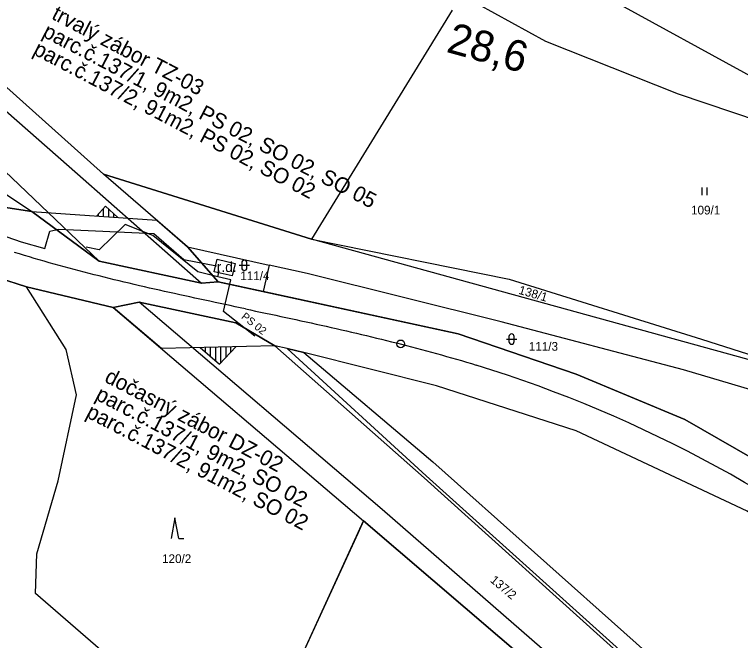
# Model space of a CAD drawing. Extents: x -794765 to -785424, y -1118958 to -1108731.
# Drawn here: x -789643.6 to -789502.2, y -1114356.2 to -1114234.4 of the extents above; entities that cross this region are included whole.
import ezdxf

# ---------------------------------------------------------------- set-up
doc = ezdxf.new("R2010")
doc.units = 0
for name, color, linetype in [('Level 66', 7, 'Continuous'), ('Level 73', 7, 'Continuous'), ('Level 75', 7, 'Continuous'), ('Level 76', 7, 'Continuous'), ('Level 77', 7, 'Continuous'), ('Level 81', 7, 'Continuous'), ('Vrstva 1', 7, 'Continuous'), ('Vrstva 53', 7, 'Continuous')]:
    doc.layers.add(name, color=color, linetype=linetype)

msp = doc.modelspace()

# ---------------------------------------------------------------- linework, layer by layer
at = {"layer": 'Level 66'}
for p, q in [((-789509.7, -1114269.49), (-789509.7, -1114267.99)), ((-789508.7, -1114269.49), (-789508.7, -1114267.99)), ((-789599.82, -1114283.16), (-789597.81, -1114283.16)), ((-789599.32, -1114282.66), (-789599.32, -1114283.66)), ((-789598.31, -1114283.66), (-789598.31, -1114282.66)), ((-789547.79, -1114297.52), (-789545.79, -1114297.52)), ((-789547.29, -1114297.02), (-789547.29, -1114298.02)), ((-789546.29, -1114298.02), (-789546.29, -1114297.02)), ((-789612.34, -1114332.34), (-789613.09, -1114336.34)), ((-789611.59, -1114336.34), (-789612.34, -1114332.34)), ((-789611.59, -1114336.34), (-789610.59, -1114336.34))]:
    msp.add_line(p, q, dxfattribs=at)
for centre, start, end in [((-789598.82, -1114282.66), 0, 180), ((-789598.82, -1114283.66), 180, 359.9879), ((-789546.79, -1114297.02), 0, 180), ((-789546.79, -1114298.02), 180, 359.9879)]:
    msp.add_arc(centre, 0.5, start, end, dxfattribs=at)
at = {"layer": 'Level 75'}
for p, q in [((-789495.83, -1114248.83), (-789550.41, -1114218.8)), ((-789558.36, -1114233.53), (-789585.72, -1114278.05)), ((-789652.15, -1114264.75), (-789640.19, -1114272.7)), ((-789609.87, -1114279.55), (-789626.24, -1114265.44)), ((-789585.72, -1114278.05), (-789626.24, -1114265.44)), ((-789672.68, -1114277.31), (-789641.23, -1114287.32)), ((-789475.21, -1114308.57), (-789585.72, -1114278.05)), ((-789603.91, -1114286.39), (-789609.87, -1114279.55)), ((-789609.87, -1114279.55), (-789594.01, -1114283.11)), ((-789594.01, -1114283.11), (-789595.15, -1114288.29)), ((-789595.15, -1114288.29), (-789603.91, -1114286.39)), ((-789641.23, -1114287.32), (-789624.34, -1114291.37)), ((-789624.34, -1114291.37), (-789575.6, -1114332.86)), ((-789590.47, -1114299.37), (-789587.26, -1114300.1)), ((-789599.87, -1114385.78), (-789575.6, -1114332.86))]:
    msp.add_line(p, q, dxfattribs=at)
for points in [[(-789626.24, -1114265.44), (-789653.29, -1114241.26), (-789699.87, -1114199.39)], [(-789640.19, -1114272.7), (-789665.23, -1114268.84), (-789691.28, -1114256.01), (-789717.72, -1114240.35)], [(-789640.19, -1114272.7), (-789627.07, -1114282.33), (-789607.19, -1114286.63), (-789603.91, -1114286.39)], [(-789585.72, -1114278.05), (-789547.28, -1114285.86), (-789509.8, -1114297.51), (-789475.21, -1114308.57)], [(-789483.32, -1114312.4), (-789513.31, -1114303.51), (-789548.79, -1114294.18), (-789586.59, -1114284.77), (-789594.01, -1114283.11)], [(-789599.87, -1114385.78), (-789620.14, -1114369.54), (-789622.91, -1114361.34), (-789639.49, -1114347.05), (-789639.25, -1114339.29), (-789635.04, -1114325.1), (-789631.47, -1114308.38), (-789633.53, -1114299.52), (-789641.23, -1114287.32)], [(-789496.46, -1114322.71), (-789513.07, -1114313.2), (-789534.19, -1114304.37), (-789557.19, -1114296.51), (-789595.15, -1114288.29)], [(-789590.47, -1114299.37), (-789592.9, -1114298.82), (-789600.46, -1114294.39), (-789619.3, -1114290.36), (-789624.34, -1114291.37)], [(-789411.55, -1114487.64), (-789444.12, -1114440.1), (-789460.39, -1114416.23), (-789471.74, -1114406.17), (-789505.63, -1114376.09), (-789563.4, -1114324.15), (-789590.47, -1114299.37)], [(-789587.26, -1114300.1), (-789562.09, -1114321.4), (-789502.74, -1114374.33), (-789470.17, -1114403.72), (-789452.65, -1114419.15), (-789441.48, -1114438.37), (-789411.55, -1114487.64)], [(-789387.36, -1114439.86), (-789400.13, -1114420.69), (-789449.47, -1114371.56), (-789470.68, -1114352.09), (-789500.91, -1114330.99), (-789534.18, -1114315.38), (-789561.38, -1114306.6), (-789587.26, -1114300.1)], [(-789575.6, -1114332.86), (-789515.81, -1114384.07), (-789480.88, -1114415.35), (-789466.19, -1114428.84), (-789454.55, -1114445.52), (-789423.09, -1114499.54)]]:
    msp.add_lwpolyline(points, dxfattribs=at)
at = {"layer": 'Level 77'}
for p, q in [((-789656.61, -1114243.22), (-789631.32, -1114265.33)), ((-789627.07, -1114282.33), (-789662.93, -1114248.27)), ((-789631.32, -1114265.33), (-789607.19, -1114286.63)), ((-789572, -1114330.7), (-789619.3, -1114290.36)), ((-789592.9, -1114298.82), (-789563.81, -1114324.53)), ((-789563.81, -1114324.53), (-789505.98, -1114376.61)), ((-789512.77, -1114382.14), (-789572, -1114330.7))]:
    msp.add_line(p, q, dxfattribs=at)
at = {"layer": 'Level 81'}
for points in [[(-789863.72, -1114054.97), (-789859.91, -1114056.9), (-789828.1, -1114085.48), (-789766.83, -1114142.08), (-789706.12, -1114193.77), (-789699.87, -1114199.39), (-789653.29, -1114241.26), (-789626.24, -1114265.44), (-789585.72, -1114278.05), (-789547.28, -1114285.86), (-789509.8, -1114297.51), (-789475.21, -1114308.57), (-789456.17, -1114314.65), (-789451.67, -1114316.09), (-789445.82, -1114299.21), (-789436.06, -1114282.16), (-789435.21, -1114282.44), (-789432.19, -1114273.58), (-789444.18, -1114268.92), (-789455.16, -1114266.24)], [(-789455.16, -1114266.24), (-789471.09, -1114264.39), (-789472.14, -1114264.04), (-789514.28, -1114249.87), (-789540.11, -1114239.63), (-789556.69, -1114230.44)], [(-789400.13, -1114420.69), (-789449.47, -1114371.56), (-789470.68, -1114352.09), (-789500.91, -1114330.99), (-789534.18, -1114315.38), (-789561.38, -1114306.6), (-789587.26, -1114300.1), (-789562.09, -1114321.4), (-789502.74, -1114374.33), (-789470.17, -1114403.72), (-789452.65, -1114419.15), (-789441.48, -1114438.37), (-789411.55, -1114487.64), (-789407.91, -1114493.28)], [(-789417.6, -1114507.26), (-789420.43, -1114503.28), (-789423.09, -1114499.54), (-789454.55, -1114445.52), (-789466.19, -1114428.84), (-789480.88, -1114415.35), (-789515.81, -1114384.07), (-789575.6, -1114332.86), (-789576.73, -1114335.33), (-789599.87, -1114385.78), (-789603.26, -1114393.19), (-789604.86, -1114396.67)]]:
    msp.add_lwpolyline(points, dxfattribs=at)
at = {"layer": 'Vrstva 1'}
for p, q in [((-789627.58, -1114273.58), (-789625.82, -1114271.66)), ((-789626.21, -1114273.68), (-789626.21, -1114272.09)), ((-789625.82, -1114271.66), (-789623.43, -1114273.87)), ((-789625.21, -1114273.75), (-789625.21, -1114272.22)), ((-789640.19, -1114272.7), (-789627.07, -1114282.33)), ((-789640.19, -1114272.7), (-789615.84, -1114274.4)), ((-789627.21, -1114273.61), (-789627.21, -1114273.18)), ((-789624.21, -1114273.82), (-789624.21, -1114273.15)), ((-789637.05, -1114275), (-789637.05, -1114275)), ((-789622.02, -1114275.21), (-789627.1, -1114280.14)), ((-789622.02, -1114275.21), (-789627.1, -1114280.14)), ((-789616.62, -1114277.34), (-789622.02, -1114275.21)), ((-789607.89, -1114284.46), (-789616.62, -1114277.34)), ((-789627.1, -1114280.14), (-789629.63, -1114279.65)), ((-789627.1, -1114280.14), (-789629.63, -1114279.65)), ((-789609.87, -1114279.55), (-789609.87, -1114279.55)), ((-789609.87, -1114279.55), (-789603.91, -1114286.39)), ((-789627.07, -1114282.33), (-789607.19, -1114286.63)), ((-789604.67, -1114284.43), (-789604.11, -1114282)), ((-789604.67, -1114284.43), (-789604.11, -1114282)), ((-789604.11, -1114282), (-789600.6, -1114282.8)), ((-789604.11, -1114282), (-789600.6, -1114282.8)), ((-789600.6, -1114282.8), (-789601.16, -1114285.24)), ((-789600.6, -1114282.8), (-789601.16, -1114285.24)), ((-789604, -1114285.39), (-789607.89, -1114284.46)), ((-789604, -1114285.39), (-789607.89, -1114284.46)), ((-789604, -1114285.39), (-789607.89, -1114284.46)), ((-789601.16, -1114285.24), (-789604.67, -1114284.43)), ((-789601.16, -1114285.24), (-789604.67, -1114284.43)), ((-789607.19, -1114286.63), (-789603.91, -1114286.39)), ((-789624.34, -1114291.37), (-789619.3, -1114290.36)), ((-789619.3, -1114290.36), (-789600.46, -1114294.39)), ((-789602.15, -1114294.03), (-789602.15, -1114294.03)), ((-789600.46, -1114294.39), (-789592.9, -1114298.82)), ((-789592.9, -1114298.82), (-789614.97, -1114299.35)), ((-789607.41, -1114299.17), (-789603.64, -1114302.43)), ((-789606.38, -1114300.06), (-789606.38, -1114299.14)), ((-789605.38, -1114300.92), (-789605.38, -1114299.12)), ((-789604.38, -1114301.79), (-789604.38, -1114299.09)), ((-789603.64, -1114302.43), (-789600.5, -1114299)), ((-789603.38, -1114302.15), (-789603.38, -1114299.07)), ((-789602.38, -1114301.05), (-789602.38, -1114299.05)), ((-789601.42, -1114300.01), (-789601.42, -1114299.02))]:
    msp.add_line(p, q, dxfattribs=at)
for points in [[(-789729.37, -1114235.18), (-789723.86, -1114238), (-789721.43, -1114240.25), (-789715.58, -1114243.5), (-789712.53, -1114244.57), (-789693.8, -1114256.22), (-789674.69, -1114266.08), (-789667.23, -1114269.28), (-789659.83, -1114272.47), (-789642.29, -1114278.58), (-789637.66, -1114279.92), (-789636.67, -1114276.5), (-789634.93, -1114276.11), (-789616.44, -1114277), (-789610.6, -1114282.06), (-789604.23, -1114283.25)], [(-789729.37, -1114235.18), (-789723.86, -1114238), (-789721.43, -1114240.25), (-789715.58, -1114243.5), (-789712.53, -1114244.57), (-789693.8, -1114256.22), (-789674.69, -1114266.08), (-789667.23, -1114269.28), (-789659.83, -1114272.47), (-789642.29, -1114278.58), (-789637.66, -1114279.92), (-789636.67, -1114276.5), (-789634.93, -1114276.11), (-789616.44, -1114277), (-789610.6, -1114282.06), (-789604.23, -1114283.25)], [(-789667.23, -1114269.28), (-789659.83, -1114272.47), (-789642.29, -1114278.58), (-789637.66, -1114279.92), (-789636.67, -1114276.5), (-789634.93, -1114276.11), (-789616.44, -1114277), (-789610.6, -1114282.06), (-789604.23, -1114283.25)], [(-789667.23, -1114269.28), (-789659.83, -1114272.47), (-789642.29, -1114278.58), (-789637.66, -1114279.92), (-789636.67, -1114276.5), (-789634.93, -1114276.11), (-789616.44, -1114277), (-789610.6, -1114282.06), (-789604.23, -1114283.25)], [(-789667.23, -1114269.28), (-789659.83, -1114272.47), (-789642.29, -1114278.58), (-789637.66, -1114279.92), (-789636.67, -1114276.5), (-789634.93, -1114276.11), (-789616.44, -1114277), (-789610.6, -1114282.06), (-789604.23, -1114283.25)], [(-789598.62, -1114291.64), (-789599.6, -1114291.43), (-789600.58, -1114291.22), (-789601.57, -1114291.01), (-789602.55, -1114290.8), (-789603.54, -1114290.59), (-789604.52, -1114290.38), (-789605.51, -1114290.17), (-789606.49, -1114289.96), (-789607.47, -1114289.75), (-789608.46, -1114289.54), (-789609.44, -1114289.33), (-789610.42, -1114289.11), (-789611.41, -1114288.9), (-789612.39, -1114288.68), (-789613.37, -1114288.46), (-789614.35, -1114288.24), (-789615.34, -1114288.02), (-789616.32, -1114287.8), (-789617.3, -1114287.58), (-789618.28, -1114287.35), (-789619.26, -1114287.13), (-789620.24, -1114286.9), (-789621.22, -1114286.67), (-789622.2, -1114286.43), (-789623.18, -1114286.2), (-789624.16, -1114285.96), (-789625.13, -1114285.73), (-789626.11, -1114285.48), (-789627.09, -1114285.24), (-789628.06, -1114284.99), (-789629.04, -1114284.75), (-789630.01, -1114284.5), (-789630.99, -1114284.24), (-789631.96, -1114283.98), (-789632.93, -1114283.73), (-789633.9, -1114283.46), (-789634.87, -1114283.2), (-789635.84, -1114282.93), (-789636.81, -1114282.66), (-789637.78, -1114282.38), (-789638.75, -1114282.1), (-789639.71, -1114281.82), (-789640.68, -1114281.53), (-789641.64, -1114281.25), (-789642.6, -1114280.95), (-789643.57, -1114280.66)], [(-789598.62, -1114291.64), (-789599.6, -1114291.43), (-789600.58, -1114291.22), (-789601.57, -1114291.01), (-789602.55, -1114290.8), (-789603.54, -1114290.59), (-789604.52, -1114290.38), (-789605.51, -1114290.17), (-789606.49, -1114289.96), (-789607.47, -1114289.75), (-789608.46, -1114289.54), (-789609.44, -1114289.33), (-789610.42, -1114289.11), (-789611.41, -1114288.9), (-789612.39, -1114288.68), (-789613.37, -1114288.46), (-789614.35, -1114288.24), (-789615.34, -1114288.02), (-789616.32, -1114287.8), (-789617.3, -1114287.58), (-789618.28, -1114287.35), (-789619.26, -1114287.13), (-789620.24, -1114286.9), (-789621.22, -1114286.67), (-789622.2, -1114286.43), (-789623.18, -1114286.2), (-789624.16, -1114285.96), (-789625.13, -1114285.73), (-789626.11, -1114285.48), (-789627.09, -1114285.24), (-789628.06, -1114284.99), (-789629.04, -1114284.75), (-789630.01, -1114284.5), (-789630.99, -1114284.24), (-789631.96, -1114283.98), (-789632.93, -1114283.73), (-789633.9, -1114283.46), (-789634.87, -1114283.2), (-789635.84, -1114282.93), (-789636.81, -1114282.66), (-789637.78, -1114282.38), (-789638.75, -1114282.1), (-789639.71, -1114281.82), (-789640.68, -1114281.53), (-789641.64, -1114281.25), (-789642.6, -1114280.95), (-789643.57, -1114280.66)], [(-789598.62, -1114291.64), (-789599.6, -1114291.43), (-789600.58, -1114291.22), (-789601.57, -1114291.01), (-789602.55, -1114290.8), (-789603.54, -1114290.59), (-789604.52, -1114290.38), (-789605.51, -1114290.17), (-789606.49, -1114289.96), (-789607.47, -1114289.75), (-789608.46, -1114289.54), (-789609.44, -1114289.33), (-789610.42, -1114289.11), (-789611.41, -1114288.9), (-789612.39, -1114288.68), (-789613.37, -1114288.46), (-789614.35, -1114288.24), (-789615.34, -1114288.02), (-789616.32, -1114287.8), (-789617.3, -1114287.58), (-789618.28, -1114287.35), (-789619.26, -1114287.13), (-789620.24, -1114286.9), (-789621.22, -1114286.67), (-789622.2, -1114286.43), (-789623.18, -1114286.2), (-789624.16, -1114285.96), (-789625.13, -1114285.73), (-789626.11, -1114285.48), (-789627.09, -1114285.24), (-789628.06, -1114284.99), (-789629.04, -1114284.75), (-789630.01, -1114284.5), (-789630.99, -1114284.24), (-789631.96, -1114283.98), (-789632.93, -1114283.73), (-789633.9, -1114283.46), (-789634.87, -1114283.2), (-789635.84, -1114282.93), (-789636.81, -1114282.66), (-789637.78, -1114282.38), (-789638.75, -1114282.1), (-789639.71, -1114281.82), (-789640.68, -1114281.53), (-789641.64, -1114281.25), (-789642.6, -1114280.95), (-789643.57, -1114280.66)], [(-789598.62, -1114291.64), (-789599.6, -1114291.43), (-789600.58, -1114291.22), (-789601.57, -1114291.01), (-789602.55, -1114290.8), (-789603.54, -1114290.59), (-789604.52, -1114290.38), (-789605.51, -1114290.17), (-789606.49, -1114289.96), (-789607.47, -1114289.75), (-789608.46, -1114289.54), (-789609.44, -1114289.33), (-789610.42, -1114289.11), (-789611.41, -1114288.9), (-789612.39, -1114288.68), (-789613.37, -1114288.46), (-789614.35, -1114288.24), (-789615.34, -1114288.02), (-789616.32, -1114287.8), (-789617.3, -1114287.58), (-789618.28, -1114287.35), (-789619.26, -1114287.13), (-789620.24, -1114286.9), (-789621.22, -1114286.67), (-789622.2, -1114286.43), (-789623.18, -1114286.2), (-789624.16, -1114285.96), (-789625.13, -1114285.73), (-789626.11, -1114285.48), (-789627.09, -1114285.24), (-789628.06, -1114284.99), (-789629.04, -1114284.75), (-789630.01, -1114284.5), (-789630.99, -1114284.24), (-789631.96, -1114283.98), (-789632.93, -1114283.73), (-789633.9, -1114283.46), (-789634.87, -1114283.2), (-789635.84, -1114282.93), (-789636.81, -1114282.66), (-789637.78, -1114282.38), (-789638.75, -1114282.1), (-789639.71, -1114281.82), (-789640.68, -1114281.53), (-789641.64, -1114281.25), (-789642.6, -1114280.95), (-789643.57, -1114280.66)], [(-789596.8, -1114296.95), (-789602.89, -1114292.18), (-789601.46, -1114285.96), (-789604, -1114285.39), (-789603.74, -1114284.21)], [(-789596.8, -1114296.95), (-789602.89, -1114292.18), (-789601.46, -1114285.96), (-789604, -1114285.39), (-789603.74, -1114284.21)], [(-789596.8, -1114296.95), (-789602.89, -1114292.18), (-789601.46, -1114285.96), (-789604, -1114285.39), (-789603.74, -1114284.21)], [(-789596.8, -1114296.95), (-789602.89, -1114292.18), (-789601.46, -1114285.96), (-789604, -1114285.39), (-789603.74, -1114284.21)], [(-789598.62, -1114291.64), (-789597.63, -1114291.85), (-789596.65, -1114292.06), (-789595.66, -1114292.26), (-789594.68, -1114292.47), (-789593.69, -1114292.68), (-789592.71, -1114292.89), (-789591.73, -1114293.1), (-789590.74, -1114293.31), (-789589.76, -1114293.53), (-789588.77, -1114293.74), (-789587.79, -1114293.95), (-789586.81, -1114294.17), (-789585.82, -1114294.38), (-789584.84, -1114294.6), (-789583.86, -1114294.81), (-789582.88, -1114295.03), (-789581.9, -1114295.25), (-789580.91, -1114295.47), (-789579.93, -1114295.7), (-789578.95, -1114295.92), (-789577.97, -1114296.15), (-789576.99, -1114296.38), (-789576.01, -1114296.61), (-789575.03, -1114296.84), (-789574.05, -1114297.07), (-789573.07, -1114297.31), (-789572.1, -1114297.55), (-789571.12, -1114297.79), (-789570.14, -1114298.03), (-789569.17, -1114298.27), (-789568.19, -1114298.52), (-789567.22, -1114298.77), (-789566.24, -1114299.03), (-789565.27, -1114299.28), (-789564.3, -1114299.54), (-789563.33, -1114299.8), (-789562.35, -1114300.07), (-789561.38, -1114300.33), (-789560.42, -1114300.6), (-789559.45, -1114300.88), (-789558.48, -1114301.15), (-789557.51, -1114301.44), (-789556.55, -1114301.72), (-789555.58, -1114302.01), (-789554.62, -1114302.3), (-789553.66, -1114302.59)], [(-789598.62, -1114291.64), (-789597.63, -1114291.85), (-789596.65, -1114292.06), (-789595.66, -1114292.26), (-789594.68, -1114292.47), (-789593.69, -1114292.68), (-789592.71, -1114292.89), (-789591.73, -1114293.1), (-789590.74, -1114293.31), (-789589.76, -1114293.53), (-789588.77, -1114293.74), (-789587.79, -1114293.95), (-789586.81, -1114294.17), (-789585.82, -1114294.38), (-789584.84, -1114294.6), (-789583.86, -1114294.81), (-789582.88, -1114295.03), (-789581.9, -1114295.25), (-789580.91, -1114295.47), (-789579.93, -1114295.7), (-789578.95, -1114295.92), (-789577.97, -1114296.15), (-789576.99, -1114296.38), (-789576.01, -1114296.61), (-789575.03, -1114296.84), (-789574.05, -1114297.07), (-789573.07, -1114297.31), (-789572.1, -1114297.55), (-789571.12, -1114297.79), (-789570.14, -1114298.03), (-789569.17, -1114298.27), (-789568.19, -1114298.52), (-789567.22, -1114298.77), (-789566.24, -1114299.03), (-789565.27, -1114299.28), (-789564.3, -1114299.54), (-789563.33, -1114299.8), (-789562.35, -1114300.07), (-789561.38, -1114300.33), (-789560.42, -1114300.6), (-789559.45, -1114300.88), (-789558.48, -1114301.15), (-789557.51, -1114301.44), (-789556.55, -1114301.72), (-789555.58, -1114302.01), (-789554.62, -1114302.3), (-789553.66, -1114302.59)], [(-789598.62, -1114291.64), (-789597.63, -1114291.85), (-789596.65, -1114292.06), (-789595.66, -1114292.26), (-789594.68, -1114292.47), (-789593.69, -1114292.68), (-789592.71, -1114292.89), (-789591.73, -1114293.1), (-789590.74, -1114293.31), (-789589.76, -1114293.53), (-789588.77, -1114293.74), (-789587.79, -1114293.95), (-789586.81, -1114294.17), (-789585.82, -1114294.38), (-789584.84, -1114294.6), (-789583.86, -1114294.81), (-789582.88, -1114295.03), (-789581.9, -1114295.25), (-789580.91, -1114295.47), (-789579.93, -1114295.7), (-789578.95, -1114295.92), (-789577.97, -1114296.15), (-789576.99, -1114296.38), (-789576.01, -1114296.61), (-789575.03, -1114296.84), (-789574.05, -1114297.07), (-789573.07, -1114297.31), (-789572.1, -1114297.55), (-789571.12, -1114297.79), (-789570.14, -1114298.03), (-789569.17, -1114298.27), (-789568.19, -1114298.52), (-789567.22, -1114298.77), (-789566.24, -1114299.03), (-789565.27, -1114299.28), (-789564.3, -1114299.54), (-789563.33, -1114299.8), (-789562.35, -1114300.07), (-789561.38, -1114300.33), (-789560.42, -1114300.6), (-789559.45, -1114300.88), (-789558.48, -1114301.15), (-789557.51, -1114301.44), (-789556.55, -1114301.72), (-789555.58, -1114302.01), (-789554.62, -1114302.3), (-789553.66, -1114302.59)], [(-789598.62, -1114291.64), (-789597.63, -1114291.85), (-789596.65, -1114292.06), (-789595.66, -1114292.26), (-789594.68, -1114292.47), (-789593.69, -1114292.68), (-789592.71, -1114292.89), (-789591.73, -1114293.1), (-789590.74, -1114293.31), (-789589.76, -1114293.53), (-789588.77, -1114293.74), (-789587.79, -1114293.95), (-789586.81, -1114294.17), (-789585.82, -1114294.38), (-789584.84, -1114294.6), (-789583.86, -1114294.81), (-789582.88, -1114295.03), (-789581.9, -1114295.25), (-789580.91, -1114295.47), (-789579.93, -1114295.7), (-789578.95, -1114295.92), (-789577.97, -1114296.15), (-789576.99, -1114296.38), (-789576.01, -1114296.61), (-789575.03, -1114296.84), (-789574.05, -1114297.07), (-789573.07, -1114297.31), (-789572.1, -1114297.55), (-789571.12, -1114297.79), (-789570.14, -1114298.03), (-789569.17, -1114298.27), (-789568.19, -1114298.52), (-789567.22, -1114298.77), (-789566.24, -1114299.03), (-789565.27, -1114299.28), (-789564.3, -1114299.54), (-789563.33, -1114299.8), (-789562.35, -1114300.07), (-789561.38, -1114300.33), (-789560.42, -1114300.6), (-789559.45, -1114300.88), (-789558.48, -1114301.15), (-789557.51, -1114301.44), (-789556.55, -1114301.72), (-789555.58, -1114302.01), (-789554.62, -1114302.3), (-789553.66, -1114302.59)]]:
    msp.add_lwpolyline(points, dxfattribs=at)
for points in [[(-789640.19, -1114272.7), (-789615.84, -1114274.4), (-789609.87, -1114279.55), (-789603.91, -1114286.39), (-789607.19, -1114286.63), (-789627.07, -1114282.33)], [(-789624.34, -1114291.37), (-789619.3, -1114290.36), (-789600.46, -1114294.39), (-789592.9, -1114298.82), (-789614.97, -1114299.35)]]:
    msp.add_lwpolyline(points, close=True, dxfattribs=at)
msp.add_circle((-789568.38, -1114298.45), 0.75, dxfattribs=at)
msp.add_arc((-789628.9, -1114546.24), 255, 50.0141, 72.8377, dxfattribs=at)
msp.add_arc((-789628.9, -1114546.24), 255, 50.0141, 72.8377, dxfattribs=at)
msp.add_arc((-789628.9, -1114546.24), 255, 50.0141, 72.8377, dxfattribs=at)
at = {"layer": 'Vrstva 53'}
for points in [[(-790049.23, -1114034.44), (-790014.82, -1114057.41), (-790011.64, -1114059.53), (-790007.66, -1114062.18), (-790004.95, -1114067.14), (-789993.35, -1114088.34), (-789984.83, -1114079.42), (-789951.34, -1114096.74), (-789913.42, -1114129.06), (-789891.43, -1114142.08), (-789830.15, -1114178.38), (-789746.5, -1114225.43), (-789721.98, -1114237.82), (-789717.72, -1114240.35), (-789691.28, -1114256.01), (-789665.23, -1114268.84), (-789640.19, -1114272.7), (-789627.07, -1114282.33), (-789607.19, -1114286.63), (-789603.91, -1114286.39)], [(-789600.46, -1114294.39), (-789619.3, -1114290.36), (-789624.34, -1114291.37), (-789641.23, -1114287.32), (-789672.68, -1114277.31), (-789675.34, -1114276.11), (-789724.61, -1114250.58), (-789730.23, -1114243.59), (-789790.24, -1114210.69), (-789844.34, -1114181.96), (-789891.39, -1114158.73), (-789943.99, -1114130.82), (-789972.38, -1114117.19), (-789989.47, -1114115.38), (-790009.42, -1114105.25), (-790039.99, -1114089.61), (-790043.48, -1114088.64), (-790052.2, -1114080.82), (-790070.36, -1114064.18)], [(-789603.91, -1114286.39), (-789557.19, -1114296.51), (-789534.19, -1114304.37), (-789513.07, -1114313.2), (-789496.46, -1114322.71), (-789491.56, -1114325.89), (-789478.18, -1114334.57), (-789448.8, -1114359.16), (-789421.56, -1114385.77), (-789401.5, -1114405.4), (-789396.12, -1114409.35), (-789381.93, -1114424.44), (-789378.22, -1114428.46), (-789362.04, -1114444), (-789354.83, -1114451.89), (-789355.6, -1114453.64), (-789352.15, -1114456.75), (-789350.58, -1114455.19), (-789342.35, -1114454.54), (-789329.78, -1114474.08), (-789314.84, -1114486.39)], [(-789332.87, -1114495.13), (-789342.11, -1114483.58), (-789343.4, -1114478.53), (-789356.86, -1114462.31), (-789355.65, -1114460.93), (-789359, -1114457.59), (-789360.15, -1114458.92), (-789383.79, -1114436.65), (-789387.36, -1114439.86), (-789400.13, -1114420.69), (-789449.47, -1114371.56), (-789470.68, -1114352.09), (-789500.91, -1114330.99), (-789534.18, -1114315.38), (-789561.38, -1114306.6), (-789587.26, -1114300.1), (-789590.47, -1114299.37), (-789592.9, -1114298.82), (-789600.46, -1114294.39)]]:
    msp.add_lwpolyline(points, dxfattribs=at)

# ---------------------------------------------------------------- texts
at = {"layer": 'Level 73'}
msp.add_text('28,6', height=6, rotation=344.507, dxfattribs=at).set_placement((-789559.69, -1114241.59))
at = {"layer": 'Level 76'}
for s, p in [('109/1', (-789511.84, -1114273.27)), ('111/4', (-789599.61, -1114286.05)), ('111/3', (-789543.43, -1114299.79)), ('120/2', (-789614.84, -1114341.11))]:
    msp.add_text(s, height=1.7, dxfattribs=at).set_placement(p)
for s, rotation, p in [('138/1', 344, (-789545.54, -1114288.69)), ('137/2', 320, (-789551.08, -1114344.66))]:
    msp.add_text(s, height=1.7, rotation=rotation, dxfattribs=at).set_placement(p)
at = {"layer": 'Vrstva 1'}
for s, height, rotation, p in [('trvalý zábor TZ-03', 3, 332.3541, (-789636.53, -1114235.11)), ('parc.č.137/1, 9m2, PS 02, SO 02, SO 05', 3, 332.3541, (-789638.33, -1114238.55)), ('parc.č.137/2, 91m2, PS 02, SO 02 ', 3, 332.3541, (-789640.14, -1114241.99)), ('PS 02', 1.5, 321.472, (-789599.53, -1114293.38)), ('dočasný zábor DZ-02', 3, 332.3541, (-789626.24, -1114305.73)), ('parc.č.137/1, 9m2, SO 02', 3, 332.3541, (-789628.04, -1114309.17)), ('parc.č.137/2, 91m2, SO 02', 3, 332.3541, (-789629.85, -1114312.61))]:
    msp.add_text(s, height=height, rotation=rotation, dxfattribs=at).set_placement(p)
msp.add_text('r.d.', height=2, dxfattribs=at).set_placement((-789604.18, -1114284.47))

doc.saveas('drawing.dxf')
